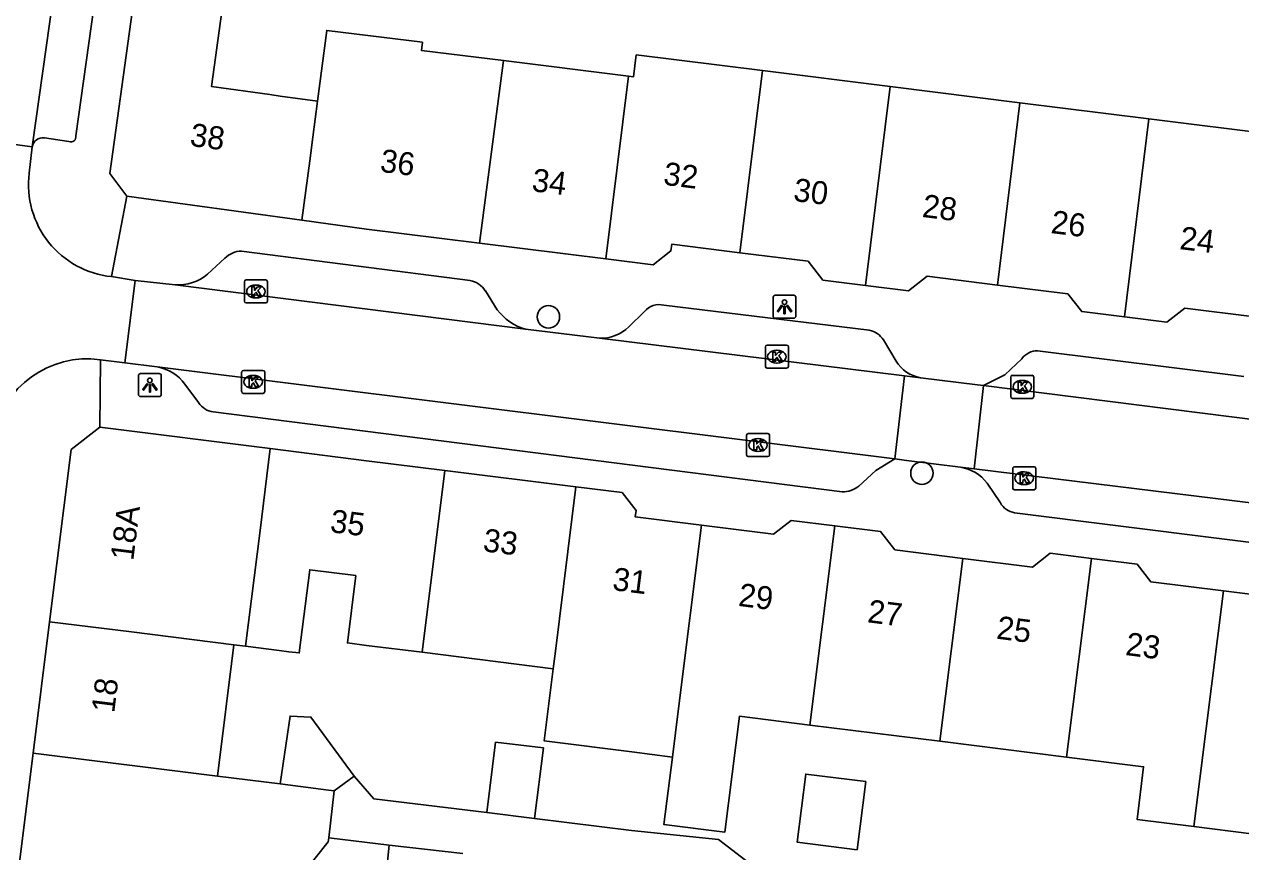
# Model space of a CAD drawing. Extents: x 161696 to 162377, y 380761 to 381673.
# Drawn here: x 161985.1 to 162038, y 381385.8 to 381421.8 of the extents above; entities that cross this region are included whole.
import ezdxf

# ---------------------------------------------------------------- set-up
doc = ezdxf.new("R2010")
doc.units = 0
for name, color, linetype in [('IMGEO_Boom', 7, 'Continuous'), ('IMGEO_Kolk', 7, 'Continuous'), ('IMGEO_Lichtpunt', 7, 'Continuous'), ('IMGEO_Pand', 7, 'Continuous'), ('IMGEO_Pand_nummerreeks', 7, 'Continuous'), ('IMGEO_Rijbaan_lokaal_open', 7, 'Continuous'), ('IMGEO_Voetpad_open', 7, 'Continuous')]:
    doc.layers.add(name, color=color, linetype=linetype)

msp = doc.modelspace()

# ---------------------------------------------------------------- linework, layer by layer
at = {"layer": 'IMGEO_Boom'}
for centre in [(162007.904, 381409.063), (162024.147, 381402.267)]:
    msp.add_circle(centre, 0.489, dxfattribs=at)
at = {"layer": 'IMGEO_Kolk'}
for p, q in [((161994.685, 381409.739), (161994.685, 381410.591)), ((161994.76, 381410.665), (161995.612, 381410.665)), ((161995.173, 381410.445), (161995.198, 381410.445)), ((161995.686, 381410.591), (161995.686, 381409.739)), ((161995.196, 381409.885), (161995.171, 381409.885)), ((161995.612, 381409.665), (161994.76, 381409.665)), ((162017.338, 381406.908), (162017.338, 381407.76)), ((162017.413, 381407.834), (162018.265, 381407.834)), ((162017.826, 381407.614), (162017.851, 381407.614)), ((162018.339, 381407.76), (162018.339, 381406.908)), ((161994.567, 381405.811), (161994.567, 381406.663)), ((161994.642, 381406.737), (161995.494, 381406.737)), ((161995.568, 381406.663), (161995.568, 381405.811)), ((162018.265, 381406.834), (162017.413, 381406.834)), ((162017.849, 381407.054), (162017.824, 381407.054)), ((161995.055, 381406.517), (161995.08, 381406.517)), ((162028.011, 381405.594), (162028.011, 381406.446)), ((162028.086, 381406.52), (162028.938, 381406.52)), ((162028.499, 381406.3), (162028.524, 381406.3)), ((162029.012, 381406.446), (162029.012, 381405.594)), ((161995.494, 381405.737), (161994.642, 381405.737)), ((161995.078, 381405.957), (161995.053, 381405.957)), ((162028.938, 381405.52), (162028.086, 381405.52)), ((162028.522, 381405.74), (162028.497, 381405.74)), ((162016.519, 381403.063), (162016.519, 381403.915)), ((162016.594, 381403.989), (162017.446, 381403.989)), ((162017.52, 381403.915), (162017.52, 381403.063)), ((162017.007, 381403.769), (162017.032, 381403.769)), ((162017.446, 381402.989), (162016.594, 381402.989)), ((162017.03, 381403.209), (162017.005, 381403.209)), ((162028.093, 381401.623), (162028.093, 381402.475)), ((162028.168, 381402.549), (162029.02, 381402.549)), ((162028.581, 381402.329), (162028.606, 381402.329)), ((162029.094, 381402.475), (162029.094, 381401.623)), ((162029.02, 381401.549), (162028.168, 381401.549)), ((162028.604, 381401.769), (162028.579, 381401.769))]:
    msp.add_line(p, q, dxfattribs=at)
for points in [[(161994.685, 381409.739), (161994.685, 381410.591)], [(161994.76, 381410.665), (161995.612, 381410.665)], [(161995.006, 381410.365), (161995.129, 381410.365), (161995.129, 381410.214), (161995.259, 381410.365), (161995.423, 381410.365), (161995.277, 381410.214), (161995.43, 381409.965), (161995.278, 381409.965), (161995.193, 381410.129), (161995.129, 381410.062), (161995.129, 381409.965), (161995.006, 381409.965), (161995.006, 381410.365)], [(161995.686, 381410.591), (161995.686, 381409.739)], [(161995.612, 381409.665), (161994.76, 381409.665)], [(162017.338, 381406.908), (162017.338, 381407.76)], [(162017.413, 381407.834), (162018.265, 381407.834)], [(162018.339, 381407.76), (162018.339, 381406.908)], [(162017.659, 381407.534), (162017.782, 381407.534), (162017.782, 381407.383), (162017.912, 381407.534), (162018.076, 381407.534), (162017.93, 381407.383), (162018.083, 381407.134), (162017.931, 381407.134), (162017.846, 381407.298), (162017.782, 381407.231), (162017.782, 381407.134), (162017.659, 381407.134), (162017.659, 381407.534)], [(161994.567, 381405.811), (161994.567, 381406.663)], [(161994.642, 381406.737), (161995.494, 381406.737)], [(161995.568, 381406.663), (161995.568, 381405.811)], [(162018.265, 381406.834), (162017.413, 381406.834)], [(161994.888, 381406.437), (161995.011, 381406.437), (161995.011, 381406.286), (161995.141, 381406.437), (161995.305, 381406.437), (161995.159, 381406.286), (161995.312, 381406.037), (161995.16, 381406.037), (161995.075, 381406.201), (161995.011, 381406.134), (161995.011, 381406.037), (161994.888, 381406.037), (161994.888, 381406.437)], [(162028.011, 381405.594), (162028.011, 381406.446)], [(162028.086, 381406.52), (162028.938, 381406.52)], [(162028.332, 381406.22), (162028.455, 381406.22), (162028.455, 381406.069), (162028.585, 381406.22), (162028.749, 381406.22), (162028.603, 381406.069), (162028.756, 381405.82), (162028.604, 381405.82), (162028.519, 381405.984), (162028.455, 381405.917), (162028.455, 381405.82), (162028.332, 381405.82), (162028.332, 381406.22)], [(162029.012, 381406.446), (162029.012, 381405.594)], [(161995.494, 381405.737), (161994.642, 381405.737)], [(162028.938, 381405.52), (162028.086, 381405.52)], [(162016.519, 381403.063), (162016.519, 381403.915)], [(162016.594, 381403.989), (162017.446, 381403.989)], [(162017.52, 381403.915), (162017.52, 381403.063)], [(162016.84, 381403.689), (162016.963, 381403.689), (162016.963, 381403.538), (162017.093, 381403.689), (162017.257, 381403.689), (162017.111, 381403.538), (162017.264, 381403.289), (162017.112, 381403.289), (162017.027, 381403.453), (162016.963, 381403.386), (162016.963, 381403.289), (162016.84, 381403.289), (162016.84, 381403.689)], [(162017.446, 381402.989), (162016.594, 381402.989)], [(162028.093, 381401.623), (162028.093, 381402.475)], [(162028.168, 381402.549), (162029.02, 381402.549)], [(162029.094, 381402.475), (162029.094, 381401.623)], [(162028.414, 381402.249), (162028.537, 381402.249), (162028.537, 381402.098), (162028.667, 381402.249), (162028.831, 381402.249), (162028.685, 381402.098), (162028.838, 381401.849), (162028.686, 381401.849), (162028.601, 381402.013), (162028.537, 381401.946), (162028.537, 381401.849), (162028.414, 381401.849), (162028.414, 381402.249)], [(162029.02, 381401.549), (162028.168, 381401.549)]]:
    msp.add_lwpolyline(points, dxfattribs=at)
for centre, start, end in [((161994.762, 381410.589), 91.552, 178.448), ((161994.762, 381410.589), 91.552, 178.448), ((161995.61, 381410.589), 1.552, 88.448), ((161995.61, 381410.589), 1.552, 88.448), ((161994.762, 381409.741), 181.552, 268.448), ((161994.762, 381409.741), 181.552, 268.448), ((161995.61, 381409.741), 271.552, 358.448), ((161995.61, 381409.741), 271.552, 358.448), ((162017.415, 381407.758), 91.552, 178.448), ((162017.415, 381407.758), 91.552, 178.448), ((162018.263, 381407.758), 1.552, 88.448), ((162018.263, 381407.758), 1.552, 88.448), ((161994.644, 381406.661), 91.552, 178.448), ((161994.644, 381406.661), 91.552, 178.448), ((161995.492, 381406.661), 1.552, 88.448), ((161995.492, 381406.661), 1.552, 88.448), ((162017.415, 381406.91), 181.552, 268.448), ((162017.415, 381406.91), 181.552, 268.448), ((162018.263, 381406.91), 271.552, 358.448), ((162018.263, 381406.91), 271.552, 358.448), ((162028.088, 381406.444), 91.552, 178.448), ((162028.088, 381406.444), 91.552, 178.448), ((162028.936, 381406.444), 1.552, 88.448), ((162028.936, 381406.444), 1.552, 88.448), ((161994.644, 381405.813), 181.552, 268.448), ((161994.644, 381405.813), 181.552, 268.448), ((161995.492, 381405.813), 271.552, 358.448), ((161995.492, 381405.813), 271.552, 358.448), ((162028.088, 381405.596), 181.552, 268.448), ((162028.088, 381405.596), 181.552, 268.448), ((162028.936, 381405.596), 271.552, 358.448), ((162028.936, 381405.596), 271.552, 358.448), ((162016.596, 381403.913), 91.552, 178.448), ((162016.596, 381403.913), 91.552, 178.448), ((162017.444, 381403.913), 1.552, 88.448), ((162017.444, 381403.913), 1.552, 88.448), ((162016.596, 381403.065), 181.552, 268.448), ((162016.596, 381403.065), 181.552, 268.448), ((162017.444, 381403.065), 271.552, 358.448), ((162017.444, 381403.065), 271.552, 358.448), ((162028.17, 381402.473), 91.552, 178.448), ((162028.17, 381402.473), 91.552, 178.448), ((162029.018, 381402.473), 1.552, 88.448), ((162029.018, 381402.473), 1.552, 88.448), ((162028.17, 381401.625), 181.552, 268.448), ((162028.17, 381401.625), 181.552, 268.448), ((162029.018, 381401.625), 271.552, 358.448), ((162029.018, 381401.625), 271.552, 358.448)]:
    msp.add_arc(centre, 0.0765, start, end, dxfattribs=at)
for centre, major_axis, ratio, start_param, end_param in [((161995.172, 381410.165), (-0.387, 0.002), 0.722429, 4.712389, 7.853982), ((161995.197, 381410.165), (-0.39, 0.002), 0.717154, 1.570796, 4.712389), ((162017.825, 381407.334), (-0.387, 0.002), 0.722429, 4.712389, 7.853982), ((162017.85, 381407.334), (-0.39, 0.002), 0.717154, 1.570796, 4.712389), ((161995.054, 381406.237), (-0.387, 0.002), 0.722429, 4.712389, 7.853982), ((161995.079, 381406.237), (-0.39, 0.002), 0.717154, 1.570796, 4.712389), ((162028.498, 381406.02), (-0.387, 0.002), 0.722429, 4.712389, 7.853982), ((162028.523, 381406.02), (-0.39, 0.002), 0.717154, 1.570796, 4.712389), ((162017.006, 381403.489), (-0.387, 0.002), 0.722429, 4.712389, 7.853982), ((162017.031, 381403.489), (-0.39, 0.002), 0.717154, 1.570796, 4.712389), ((162028.58, 381402.049), (-0.387, 0.002), 0.722429, 4.712389, 7.853982), ((162028.605, 381402.049), (-0.39, 0.002), 0.717154, 1.570796, 4.712389)]:
    msp.add_ellipse(centre, major_axis=major_axis, ratio=ratio, start_param=start_param, end_param=end_param, dxfattribs=at)
at = {"layer": 'IMGEO_Lichtpunt'}
for p, q in [((162017.673, 381409.904), (162017.673, 381409.097)), ((162017.673, 381409.904), (162017.673, 381409.097)), ((162018.575, 381409.999), (162017.767, 381409.999)), ((162018.575, 381409.999), (162017.767, 381409.999)), ((162018.669, 381409.097), (162018.669, 381409.904)), ((162018.669, 381409.097), (162018.669, 381409.904)), ((162017.767, 381409.003), (162018.575, 381409.003)), ((162017.767, 381409.003), (162018.575, 381409.003)), ((161990.979, 381406.596), (161990.171, 381406.596)), ((161990.979, 381406.596), (161990.171, 381406.596)), ((161990.077, 381406.501), (161990.077, 381405.694)), ((161990.077, 381406.501), (161990.077, 381405.694)), ((161991.073, 381405.694), (161991.073, 381406.501)), ((161991.073, 381405.694), (161991.073, 381406.501)), ((161990.171, 381405.6), (161990.979, 381405.6)), ((161990.171, 381405.6), (161990.979, 381405.6))]:
    msp.add_line(p, q, dxfattribs=at)
for points in [[(162018.047, 381409.568), (162018.086, 381409.54), (162017.898, 381409.278), (162017.86, 381409.305), (162018.047, 381409.568)], [(162018.149, 381409.52), (162018.196, 381409.52), (162018.196, 381409.198), (162018.149, 381409.198), (162018.149, 381409.52)], [(162018.259, 381409.54), (162018.297, 381409.567), (162018.484, 381409.305), (162018.445, 381409.277), (162018.259, 381409.54)], [(161990.451, 381406.165), (161990.49, 381406.137), (161990.302, 381405.875), (161990.264, 381405.902), (161990.451, 381406.165)], [(161990.553, 381406.117), (161990.6, 381406.117), (161990.6, 381405.795), (161990.553, 381405.795), (161990.553, 381406.117)], [(161990.663, 381406.137), (161990.701, 381406.164), (161990.888, 381405.902), (161990.849, 381405.874), (161990.663, 381406.137)]]:
    msp.add_lwpolyline(points, dxfattribs=at)
for centre in [(162018.172, 381409.702), (161990.576, 381406.299)]:
    msp.add_circle(centre, 0.0994, dxfattribs=at)
for centre, start, end in [((162017.767, 381409.904), 90, 180), ((162017.767, 381409.904), 90, 180), ((162018.575, 381409.904), 0, 90), ((162018.575, 381409.904), 0, 90), ((162017.767, 381409.097), 180, 270), ((162017.767, 381409.097), 180, 270), ((162018.575, 381409.097), 270, 0), ((162018.575, 381409.097), 270, 360), ((161990.171, 381406.501), 90, 180), ((161990.171, 381406.501), 90, 180), ((161990.979, 381406.501), 0, 90), ((161990.979, 381406.501), 0, 90), ((161990.171, 381405.694), 180, 270), ((161990.171, 381405.694), 180, 270), ((161990.979, 381405.694), 270, 0), ((161990.979, 381405.694), 270, 360)]:
    msp.add_arc(centre, 0.0946, start, end, dxfattribs=at)
at = {"layer": 'IMGEO_Pand'}
for points in [[(161989.876, 381422.84), (161988.837, 381415.288), (161989.574, 381414.314)], [(161993.707, 381422.337), (161993.258, 381419.07), (161995.79, 381418.722), (161996.237, 381418.66), (161997.866, 381418.436)], [(161997.866, 381418.436), (161998.269, 381421.513), (162002.429, 381420.996), (162002.385, 381420.645), (162005.946, 381420.202)], [(162011.391, 381419.524), (162011.608, 381419.497), (162011.727, 381420.446), (162017.211, 381419.763)], [(162005.946, 381420.202), (162004.906, 381412.269)], [(162005.946, 381420.202), (162011.391, 381419.524)], [(162017.211, 381419.763), (162016.232, 381411.85)], [(162017.211, 381419.763), (162022.768, 381419.072)], [(162010.409, 381411.585), (162011.391, 381419.524)], [(162021.698, 381410.423), (162022.768, 381419.072)], [(162022.768, 381419.072), (162028.411, 381418.369)], [(161997.866, 381418.436), (161997.661, 381416.871), (161997.526, 381415.842), (161997.189, 381413.266)], [(162028.411, 381418.369), (162027.43, 381410.442)], [(162028.411, 381418.369), (162034.016, 381417.672)], [(162034.016, 381417.672), (162032.95, 381409.058)], [(162034.016, 381417.672), (162039.59, 381416.978)], [(161997.189, 381413.266), (161989.574, 381414.314)], [(162004.906, 381412.269), (162000, 381412.88), (161997.189, 381413.266)], [(162010.409, 381411.585), (162004.906, 381412.269)], [(162016.232, 381411.85), (162013.27, 381412.219), (162013.234, 381411.929), (162012.463, 381411.329), (162010.409, 381411.585)], [(162021.698, 381410.423), (162019.839, 381410.655), (162019.196, 381411.481), (162016.232, 381411.85)], [(162027.43, 381410.442), (162024.368, 381410.824), (162023.557, 381410.192), (162021.698, 381410.423)], [(162032.95, 381409.058), (162031.094, 381409.289), (162030.492, 381410.061), (162027.43, 381410.442)], [(162038.61, 381409.058), (162035.583, 381409.435), (162034.803, 381408.827), (162032.95, 381409.058)], [(161986.216, 381395.808), (161987.152, 381403.293), (161988.398, 381404.261)], [(161988.398, 381404.261), (161995.81, 381403.335)], [(161995.81, 381403.335), (161995.365, 381399.782), (161994.735, 381394.746)], [(161995.81, 381403.335), (162000.002, 381402.811), (162003.406, 381402.385)], [(162002.417, 381394.482), (162003.406, 381402.385)], [(162003.406, 381402.385), (162009.104, 381401.673)], [(162009.104, 381401.673), (162008.21, 381394.532), (162008.115, 381393.769)], [(162009.104, 381401.673), (162011.111, 381401.422), (162011.714, 381400.646), (162011.68, 381400.368), (162014.559, 381400.008)], [(162014.559, 381400.008), (162017.69, 381399.616), (162018.462, 381400.217), (162020.359, 381399.98)], [(162014.559, 381400.008), (162013.561, 381392.036), (162013.297, 381389.93)], [(162020.359, 381399.98), (162019.275, 381391.322)], [(162020.359, 381399.98), (162022.346, 381399.732), (162022.97, 381398.929), (162025.924, 381398.56)], [(162025.924, 381398.56), (162028.95, 381398.182), (162029.73, 381398.789), (162031.52, 381398.565)], [(162024.929, 381390.615), (162025.924, 381398.56)], [(162031.52, 381398.565), (162030.439, 381389.926)], [(162031.52, 381398.565), (162033.504, 381398.317), (162034.1, 381397.552), (162037.258, 381397.157)], [(162002.417, 381394.482), (161999.997, 381394.784), (161999.165, 381394.888), (161999.531, 381397.818), (161997.526, 381398.068), (161997.073, 381394.453), (161996.625, 381394.509), (161996.196, 381394.563), (161994.735, 381394.746)], [(162035.975, 381386.905), (162037.258, 381397.157)], [(162037.258, 381397.157), (162040.14, 381396.796), (162040.934, 381397.414), (162042.957, 381397.161)], [(161985.502, 381390.099), (161986.216, 381395.808)], [(161994.223, 381394.81), (161989.774, 381395.365), (161986.216, 381395.808)], [(161994.223, 381394.81), (161993.51, 381389.099)], [(161994.735, 381394.746), (161994.223, 381394.81)], [(162008.115, 381393.769), (162002.417, 381394.482)], [(162013.297, 381389.93), (162011.531, 381390.151), (162007.953, 381390.598), (162007.722, 381390.627), (162008.115, 381393.769)], [(161996.237, 381388.759), (161996.669, 381391.708), (161997.581, 381391.666), (161999.461, 381389.101)], [(162019.275, 381391.322), (162016.214, 381391.705), (162015.583, 381386.666), (162012.93, 381386.997), (162013.297, 381389.93)], [(162024.929, 381390.615), (162019.275, 381391.322)], [(162005.225, 381387.513), (162005.608, 381390.574), (162007.685, 381390.33), (162007.3, 381387.258)], [(162030.439, 381389.926), (162024.929, 381390.615)], [(161991.69, 381377.922), (161984.678, 381383.511), (161985.502, 381390.099)], [(161985.502, 381390.099), (161993.51, 381389.099)], [(162035.975, 381386.905), (162033.5, 381387.215), (162033.786, 381389.508), (162030.439, 381389.926)], [(161993.51, 381389.099), (161996.237, 381388.759)], [(161999.461, 381389.101), (161998.594, 381388.464)], [(162021.335, 381385.903), (162018.727, 381386.229), (162019.098, 381389.191), (162021.705, 381388.865), (162021.335, 381385.903)], [(161996.237, 381388.759), (161998.341, 381388.496), (161998.594, 381388.464)], [(162041.873, 381388.497), (162038.763, 381388.886), (162038.476, 381386.593), (162035.975, 381386.905)], [(161998.594, 381388.464), (161998.354, 381386.415)], [(162007.3, 381387.258), (162005.225, 381387.513)], [(161998.354, 381386.415), (161998.334, 381386.248), (161996.631, 381384.113)], [(161996.631, 381384.113), (161998.861, 381382.335), (162000.848, 381384.828), (162000.987, 381386.106)], [(162000.987, 381386.106), (162004.183, 381385.731)]]:
    msp.add_lwpolyline(points, dxfattribs=at)
at = {"layer": 'IMGEO_Rijbaan_lokaal_open'}
for points in [[(161992.268, 381464.789), (161985.461, 381416.455)], [(161980.747, 381417.09), (161985.46, 381416.445)], [(161985.328, 381415.304), (161985.46, 381416.445)], [(161985.46, 381416.445), (161985.461, 381416.455)], [(161988.907, 381410.81), (161989.931, 381410.642)], [(161989.48, 381407.067), (161989.931, 381410.642)], [(161989.931, 381410.642), (161991.67, 381410.452)], [(161991.67, 381410.452), (162006.902, 381408.531)], [(162006.902, 381408.531), (162010.12, 381408.129)], [(162010.12, 381408.129), (162023.395, 381406.502)], [(161989.48, 381407.067), (161988.425, 381407.198)], [(161990.892, 381406.885), (161989.48, 381407.067)], [(162022.965, 381402.889), (161990.892, 381406.885)], [(162022.965, 381402.889), (162023.395, 381406.502)], [(162023.395, 381406.502), (162024.088, 381406.418)], [(162024.088, 381406.418), (162026.562, 381406.112), (162026.829, 381406.078)], [(162026.829, 381406.078), (162026.417, 381402.452)], [(162026.829, 381406.078), (162040.365, 381404.362)], [(162025.823, 381402.525), (162023.476, 381402.825), (162022.965, 381402.889)], [(162026.417, 381402.452), (162025.823, 381402.525)], [(162053.542, 381399.125), (162026.417, 381402.452)]]:
    msp.add_lwpolyline(points, dxfattribs=at)
for centre, radius, start, end in [((161989.324, 381414.814), 4.026, 173.0142, 264.0531), ((161987.855, 381403.075), 4.162, 82.1234, 169.3857)]:
    msp.add_arc(centre, radius, start, end, dxfattribs=at)
at = {"layer": 'IMGEO_Voetpad_open'}
for points in [[(161987.359, 381416.925), (161993.343, 381459.598), (161993.96, 381463.909)], [(161985.99, 381416.845), (161987.055, 381416.685)], [(161989.574, 381414.314), (161988.907, 381410.81)], [(161994.557, 381411.915), (162004.496, 381410.641)], [(161993.088, 381410.919), (161993.842, 381411.606)], [(162005.163, 381410.188), (162005.681, 381409.367)], [(162011.407, 381408.632), (162012.088, 381409.291)], [(162012.921, 381409.571), (162021.858, 381408.488)], [(162022.472, 381408.059), (162023.022, 381407.141)], [(161988.398, 381404.261), (161988.425, 381407.198)], [(162026.829, 381406.078), (162027.755, 381406.536), (162028.484, 381407.243)], [(162029.177, 381407.591), (162038.144, 381406.47)], [(161992.693, 381405.339), (161992.102, 381406.143)], [(162020.675, 381401.461), (161993.334, 381404.929)], [(162022.965, 381402.889), (162022.149, 381402.385), (162021.402, 381401.703)], [(162027.559, 381400.975), (162026.986, 381401.831)], [(162050.6, 381397.732), (162028.174, 381400.544)], [(161999.461, 381389.101), (162000.309, 381388.116), (162005.225, 381387.513)], [(162007.3, 381387.258), (162011.525, 381386.739), (162015.3, 381386.343), (162023.617, 381379.958)], [(161998.354, 381386.415), (162000.987, 381386.106)]]:
    msp.add_lwpolyline(points, dxfattribs=at)
for centre, radius, start, end in [((161985.925, 381416.38), 0.47, 81.9986, 170.7996), ((161987.144, 381416.884), 0.218, 245.8213, 10.759), ((161994.549, 381410.951), 0.964, 89.5368, 137.2081), ((161991.791, 381412.471), 2.023, 266.5721, 309.8851), ((162004.316, 381409.659), 0.998, 32.0029, 79.6315), ((162007.548, 381410.784), 2.344, 217.2033, 253.999), ((162012.725, 381408.774), 0.82, 76.1936, 140.9649), ((162010.178, 381409.878), 1.75, 268.0939, 314.6004), ((162021.623, 381407.498), 1.017, 33.4596, 76.6566), ((162024.321, 381407.909), 1.509, 210.5844, 261.1226), ((162029.193, 381406.696), 0.895, 90.9986, 142.3298), ((161990.59, 381405.036), 1.874, 36.2249, 80.7399), ((161993.433, 381405.79), 0.867, 211.3678, 263.4241), ((162025.561, 381400.765), 1.78, 36.811, 81.5372), ((162020.706, 381402.581), 1.121, 268.4223, 308.4003), ((162028.333, 381401.425), 0.895, 210.1826, 259.7708)]:
    msp.add_arc(centre, radius, start, end, dxfattribs=at)

# ---------------------------------------------------------------- texts
at = {"layer": 'IMGEO_Pand_nummerreeks'}
for s, rotation, p in [('38', 352.3911, (161992.284, 381416.498)), ('36', 352.6432, (162000.551, 381415.373)), ('32', 352.9012, (162012.87, 381414.809)), ('34', 352.9061, (162007.15, 381414.53)), ('30', 352.8923, (162018.526, 381414.104)), ('28', 352.8923, (162024.126, 381413.406)), ('26', 352.8923, (162029.723, 381412.708)), ('24', 352.8923, (162035.322, 381412.01)), ('18A', 82.8726, (161989.852, 381398.441)), ('35', 352.8781, (161998.38, 381399.709)), ('33', 352.8896, (162005.028, 381398.877)), ('31', 352.8667, (162010.656, 381397.19)), ('29', 352.7693, (162016.132, 381396.502)), ('27', 352.7701, (162021.744, 381395.79)), ('25', 352.7701, (162027.355, 381395.078)), ('23', 352.7701, (162032.966, 381394.366)), ('18', 82.8726, (161989.024, 381391.821))]:
    msp.add_text(s, height=1, rotation=rotation, dxfattribs=at).set_placement(p)

doc.saveas('drawing.dxf')
